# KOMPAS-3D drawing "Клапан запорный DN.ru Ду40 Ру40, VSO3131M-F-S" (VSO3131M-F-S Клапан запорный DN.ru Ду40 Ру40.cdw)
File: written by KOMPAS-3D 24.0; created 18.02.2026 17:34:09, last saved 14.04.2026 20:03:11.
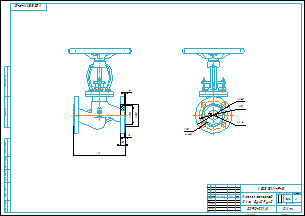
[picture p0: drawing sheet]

Document properties: Автор: R2D2; Форматы листов документа: A2; Полное имя файла: VSO3131M-F-S Клапан запорный DN.ru Ду40 Ру40.m3d; Масса: 9.54; Наименование: Клапан запорный DN.ru Ду40 Ру40; Количество листов документа: 1; Примечание: D090-02141

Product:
- Part/product: Клапан запорный DN.ru Ду40 Ру40  | designation VSO3131M-F-S
    Масса: 9.54
    Раздел спецификации: Прочие изделия
    Форматы листов документа: A2
    Примечание: D090-02141

Views: Проекционный вид 2
Referenced files in E:\Работа\Зайцев\VSO3131M-F-S Клапан запорный DN.ru Ду15-100 Ру40\DN40\: VSO3131M-F-S Клапан запорный DN.ru Ду40 Ру40.m3d
Referenced files in E:\Работа\Зайцев\Для компаса\: чертеж DN.ru А3.cdt
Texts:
  VSO3131M-F-S
  чертеж DN.ru А3.cdt
  Клапан запорный
  DN.ru Ду40 Ру40
  Клапан запорный DN.ru Ду40 Ру40
  VSO3131M-F-S Клапан запорный DN.ru Ду40 Ру40
Dimensions and other numbers on the sheet: 0; 3; 4; 145; 110; 40; 18; 4 отв.; 1:2; 1; 2; 9,54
